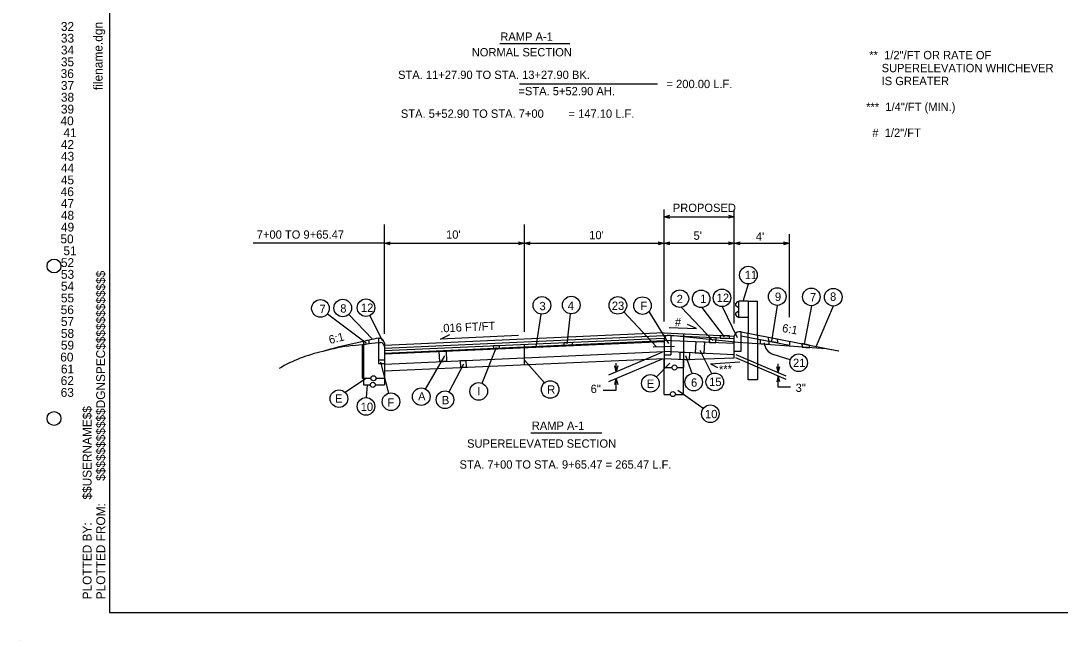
# Model space of a CAD drawing. Extents: x -210 to 558, y -150 to 205.
# Drawn here: x 417 to 491.9, y -150.3 to -105.6 of the extents above; entities that cross this region are included whole.
import ezdxf

# ---------------------------------------------------------------- set-up
doc = ezdxf.new("R2010")
doc.units = 0
for name, color, linetype in [('Level 1', 7, 'Continuous'), ('Level 32', 7, 'Continuous'), ('Level 33', 7, 'Continuous'), ('Level 34', 7, 'Continuous'), ('Level 35', 7, 'Continuous'), ('Level 36', 7, 'Continuous'), ('Level 37', 7, 'Continuous'), ('Level 38', 7, 'Continuous'), ('Level 39', 7, 'Continuous'), ('Level 4', 7, 'Continuous'), ('Level 40', 7, 'Continuous'), ('Level 41', 7, 'Continuous'), ('Level 42', 7, 'Continuous'), ('Level 43', 7, 'Continuous'), ('Level 44', 7, 'Continuous'), ('Level 45', 7, 'Continuous'), ('Level 46', 7, 'Continuous'), ('Level 47', 7, 'Continuous'), ('Level 48', 7, 'Continuous'), ('Level 49', 7, 'Continuous'), ('Level 50', 7, 'Continuous'), ('Level 51', 7, 'Continuous'), ('Level 52', 7, 'Continuous'), ('Level 53', 7, 'Continuous'), ('Level 54', 7, 'Continuous'), ('Level 55', 7, 'Continuous'), ('Level 56', 7, 'Continuous'), ('Level 57', 7, 'Continuous'), ('Level 58', 7, 'Continuous'), ('Level 59', 7, 'Continuous'), ('Level 6', 7, 'Continuous'), ('Level 60', 7, 'Continuous'), ('Level 61', 7, 'Continuous'), ('Level 62', 7, 'Continuous'), ('Level 63', 7, 'Continuous'), ('Level 7', 7, 'Continuous')]:
    doc.layers.add(name, color=color, linetype=linetype)

msp = doc.modelspace()

# ---------------------------------------------------------------- linework, layer by layer
at = {"layer": 'Level 1'}
for p, q in [((423.408, -64.342), (423.408, -148.31)), ((423.408, -148.31), (557.356, -148.31)), ((417.012, -150.31), (417.012, -150.31))]:
    msp.add_line(p, q, dxfattribs=at)
for centre in [(419.41, -123.32), (419.41, -134.316)]:
    msp.add_circle(centre, 0.5, dxfattribs=at)
at = {"layer": 'Level 4'}
for p, q in [((451.546, -107.277), (456.581, -107.277)), ((452.962, -110.192), (462.91, -110.192)), ((463.379, -127.312), (463.379, -119.248)), ((463.379, -119.766), (468.44, -119.766)), ((468.44, -127.46), (468.44, -119.248)), ((443.221, -128.224), (443.221, -120.323)), ((453.3, -120.323), (453.3, -128.073)), ((472.416, -127.011), (472.416, -121.017)), ((443.221, -121.681), (433.765, -121.681)), ((443.221, -121.681), (453.3, -121.681)), ((453.3, -121.681), (472.416, -121.681)), ((469.085, -125.864), (469.461, -124.609)), ((462.294, -126.604), (463.705, -128.917)), ((464.635, -126.302), (466.891, -128.686)), ((466.104, -126.322), (467.709, -128.435)), ((467.558, -126.247), (468.643, -128.468)), ((471.537, -126.158), (471.133, -128.733)), ((473.998, -126.182), (473.483, -128.946)), ((475.576, -126.205), (474.335, -129.112)), ((439.121, -126.759), (441.913, -128.85)), ((440.658, -126.812), (442.358, -128.602)), ((442.175, -126.895), (443.064, -128.693)), ((454.487, -126.787), (454.142, -129.143)), ((456.621, -126.766), (456.375, -128.93)), ((460.477, -126.63), (462.838, -129.148)), ((463.76, -127.746), (465.712, -127.833)), ((465.712, -127.833), (465.08, -127.529)), ((447.268, -128.589), (447.933, -128.269)), ((452.893, -128.336), (447.268, -128.589)), ((450.258, -131.776), (451.299, -129.177)), ((463.221, -129.555), (459.385, -131.187)), ((466.814, -131.089), (465.985, -129.403)), ((443.537, -132.496), (442.959, -130.262)), ((446.195, -132.195), (447.574, -129.805)), ((447.886, -132.405), (448.959, -130.367)), ((454.754, -131.75), (453.31, -130.11)), ((463.253, -130.039), (459.385, -131.685)), ((459.939, -130.951), (459.939, -130.322)), ((462.836, -131.325), (463.792, -130.325)), ((465.414, -131.069), (464.958, -129.808)), ((466.729, -130.375), (468.833, -130.225)), ((468.524, -129.93), (472.169, -131.481)), ((468.554, -129.702), (472.159, -131.236)), ((472.481, -130.097), (471.24, -129.697)), ((466.729, -130.375), (467.243, -130.639)), ((471.604, -131), (471.604, -130.37)), ((441.93, -131.418), (440.392, -132.439)), ((459.939, -132.264), (459.939, -131.449)), ((471.614, -132.06), (471.614, -131.245)), ((441.981, -131.88), (441.898, -132.812)), ((458.98, -132.264), (459.939, -132.264)), ((466.2, -133.609), (464.367, -132.309)), ((472.49, -132.06), (471.614, -132.06)), ((453.788, -135.345), (458.897, -135.345))]:
    msp.add_line(p, q, dxfattribs=at)
for points in [[(463.799, -119.882), (463.379, -119.766), (463.799, -119.654)], [(468.02, -119.65), (468.44, -119.766), (468.02, -119.878)], [(443.641, -121.797), (443.221, -121.681), (443.641, -121.569)], [(452.88, -121.565), (453.3, -121.681), (452.88, -121.793)], [(453.72, -121.797), (453.3, -121.681), (453.72, -121.569)], [(462.959, -121.565), (463.379, -121.681), (462.959, -121.793)], [(463.799, -121.797), (463.379, -121.681), (463.799, -121.569)], [(468.02, -121.565), (468.44, -121.681), (468.02, -121.793)], [(468.86, -121.797), (468.44, -121.681), (468.86, -121.569)], [(471.996, -121.565), (472.416, -121.681), (471.996, -121.793)], [(460.055, -130.531), (459.939, -130.951), (459.827, -130.531)], [(471.488, -130.58), (471.604, -131), (471.716, -130.58)], [(459.823, -131.869), (459.939, -131.449), (460.051, -131.869)], [(471.73, -131.665), (471.614, -131.245), (471.502, -131.665)]]:
    msp.add_lwpolyline(points, dxfattribs=at)
for points in [[(470.336, -128.625), (470.929, -128.742), (470.931, -128.975), (470.342, -128.935)], [(470.914, -128.455), (471.527, -128.576), (471.548, -128.867), (470.935, -128.746)], [(473.307, -128.915), (473.327, -129.18), (473.867, -129.231), (473.853, -129.034)]]:
    msp.add_lwpolyline(points, close=True, dxfattribs=at)
for centre in [(469.462, -123.975), (464.521, -125.678), (466.054, -125.69), (467.559, -125.613), (471.539, -125.524), (473.999, -125.548), (475.577, -125.571), (438.613, -126.378), (440.221, -126.352), (441.895, -126.326), (454.579, -126.16), (456.693, -126.136), (460.052, -126.16), (461.825, -126.177), (473.083, -130.297), (465.517, -131.694), (467.038, -131.682), (450.022, -132.365), (455.173, -132.226), (462.398, -131.783), (439.946, -132.89), (443.695, -133.11), (445.878, -132.744), (447.591, -132.966), (441.898, -133.446), (466.717, -133.975)]:
    msp.add_circle(centre, 0.634, dxfattribs=at)
msp.add_arc((471.57, -128.788), 0.967, 184.63452, 250.04639, dxfattribs=at)
at = {"layer": 'Level 6'}
for p, q in [((442.798, -128.83), (442.798, -130.356)), ((442.798, -128.83), (442.952, -128.83)), ((443.221, -129.418), (463.379, -128.513)), ((443.221, -129.659), (463.379, -128.754)), ((463.379, -128.513), (463.379, -130.639)), ((463.652, -128.302), (463.879, -128.302)), ((463.879, -128.302), (468.713, -128.812)), ((463.879, -128.302), (463.879, -129.718)), ((464.781, -128.213), (464.781, -130.639)), ((468.713, -128.812), (475.073, -129.274)), ((441.626, -128.976), (441.626, -131.418)), ((443.221, -129.122), (443.221, -131.418)), ((443.221, -130.393), (463.379, -129.488)), ((453.3, -128.966), (453.3, -130.438)), ((475.073, -129.274), (475.991, -129.448)), ((442.798, -130.356), (443.221, -130.356)), ((443.221, -130.89), (463.379, -129.985)), ((463.379, -129.718), (463.879, -129.718)), ((463.379, -130.639), (463.952, -130.639)), ((464.31, -130.639), (464.781, -130.639)), ((441.626, -131.418), (442.217, -131.418)), ((442.607, -131.418), (443.221, -131.418))]:
    msp.add_line(p, q, dxfattribs=at)
for centre in [(464.136, -130.639), (442.396, -131.888), (442.427, -131.419)]:
    msp.add_circle(centre, 0.183, dxfattribs=at)
for centre, radius, start, end in [((354.524, 574.72), 709.066, 276.998467, 277.151492), ((442.867, -129.178), 0.359, 8.91155, 76.24656), ((463.74, -128.654), 0.363, 103.89297, 186.01636), ((441.075, -140.015), 10.774, 102.28567, 120.31113), ((442.199, -141.09), 12.095, 96.07186, 106.45302)]:
    msp.add_arc(centre, radius, start, end, dxfattribs=at)
at = {"layer": 'Level 60'}
for points in [[(441.718, -128.964), (442.123, -128.914), (442.115, -128.661), (441.7, -128.754)], [(456.184, -129.077), (456.174, -128.837), (456.754, -128.811), (456.764, -129.051)], [(466.283, -129.619), (466.319, -128.823), (465.665, -128.793), (465.629, -129.589)], [(467.121, -128.854), (467.137, -128.5), (466.657, -128.479), (466.641, -128.833)], [(468.098, -128.545), (468.107, -128.359), (467.434, -128.329), (467.426, -128.515)], [(447.207, -130.214), (447.174, -129.482), (447.671, -129.459), (447.704, -130.192)], [(451.103, -129.305), (451.092, -129.065), (451.494, -129.047), (451.505, -129.287)], [(464.512, -130.049), (464.906, -130.067), (465.217, -130.056), (465.248, -129.578), (464.526, -129.547)], [(448.729, -130.643), (448.707, -130.147), (449.085, -130.13), (449.107, -130.626)]]:
    msp.add_lwpolyline(points, close=True, dxfattribs=at)
at = {"layer": 'Level 7'}
for p, q in [((468.687, -125.874), (468.774, -125.859)), ((469.441, -125.859), (468.774, -125.859)), ((468.774, -127.025), (468.774, -125.859)), ((469.441, -125.859), (469.441, -128.109)), ((469.441, -125.859), (470.107, -125.859)), ((470.107, -128.361), (470.107, -125.859)), ((468.539, -126.078), (468.687, -125.874)), ((468.744, -126.333), (468.554, -126.186)), ((468.554, -126.698), (468.744, -126.551)), ((468.687, -127.01), (468.539, -126.806)), ((468.687, -127.01), (468.774, -127.025)), ((469.441, -127.025), (468.774, -127.025)), ((468.938, -128.061), (468.778, -128.061)), ((468.938, -128.061), (475.955, -129.428)), ((468.938, -129.467), (468.938, -128.061)), ((469.441, -131.525), (469.441, -128.109)), ((442.798, -128.529), (442.798, -130.085)), ((442.798, -128.529), (442.89, -128.529)), ((463.377, -128.15), (443.221, -129.055)), ((443.221, -129.241), (463.356, -128.337)), ((443.221, -129.596), (463.392, -128.69)), ((463.377, -128.15), (468.438, -128.377)), ((468.46, -128.564), (463.377, -128.336)), ((463.377, -128.691), (463.377, -129.995)), ((468.424, -128.917), (463.377, -128.691)), ((468.438, -129.94), (468.438, -128.377)), ((468.938, -128.353), (472.416, -129.03)), ((470.107, -128.361), (470.107, -131.525)), ((472.416, -128.739), (472.416, -129.03)), ((441.718, -128.976), (441.718, -131.88)), ((443.221, -128.892), (443.221, -130.085)), ((462.588, -129.158), (464.13, -129.096)), ((468.438, -129.715), (463.377, -129.488)), ((468.438, -129.467), (468.938, -129.467)), ((442.798, -130.085), (443.221, -130.085)), ((443.221, -130.085), (443.221, -131.88)), ((463.377, -129.995), (464.906, -130.067)), ((463.379, -132.588), (463.379, -129.982)), ((464.786, -132.588), (464.786, -130.025)), ((464.906, -130.067), (468.438, -129.94)), ((470.107, -131.525), (469.441, -131.525)), ((441.718, -131.88), (442.213, -131.88)), ((442.578, -131.88), (443.221, -131.88)), ((463.379, -132.588), (463.841, -132.588)), ((464.2, -132.588), (464.786, -132.588))]:
    msp.add_line(p, q, dxfattribs=at)
msp.add_circle((464.02, -132.561), 0.18, dxfattribs=at)
for centre, radius, start, end in [((468.602, -126.124), 0.0781, 144.08393, 232.1285), ((468.696, -126.489), 0.0781, 307.8715, 360), ((468.602, -126.76), 0.0781, 127.8715, 215.91607), ((468.819, -128.446), 0.387, 96.02749, 169.67861), ((447.357, -157.769), 29.551, 101.48467, 106.57547), ((445.961, -146.756), 18.499, 99.84483, 104.04247), ((442.823, -128.924), 0.4, 4.50116, 80.36352)]:
    msp.add_arc(centre, radius, start, end, dxfattribs=at)

# ---------------------------------------------------------------- texts
at = {"layer": 'Level 1'}
for s, height, p in [('filename.dgn', 0.6414, (422.904, -110.628)), ('$$$$$$$$$$$DGNSPEC$$$$$$$$$$$$', 0.63883, (423.088, -138.812)), ('$$USERNAME$$', 0.63833, (422.11, -140.163)), ('PLOTTED FROM:', 0.63883, (423.095, -147.356)), ('PLOTTED BY:', 0.63883, (422.11, -147.363))]:
    msp.add_text(s, height=height, rotation=90, dxfattribs=at).set_placement(p)
at = {"layer": 'Level 32'}
msp.add_text('32', height=0.6384, dxfattribs=at).set_placement((419.904, -106.36))
at = {"layer": 'Level 33'}
msp.add_text('33', height=0.6384, dxfattribs=at).set_placement((419.904, -107.208))
at = {"layer": 'Level 34'}
msp.add_text('34', height=0.6378, dxfattribs=at).set_placement((419.904, -108.063))
at = {"layer": 'Level 35'}
msp.add_text('35', height=0.6378, dxfattribs=at).set_placement((419.904, -108.918))
at = {"layer": 'Level 36'}
msp.add_text('36', height=0.6384, dxfattribs=at).set_placement((419.888, -109.765))
at = {"layer": 'Level 37'}
msp.add_text('37', height=0.6414, dxfattribs=at).set_placement((419.904, -110.621))
at = {"layer": 'Level 38'}
msp.add_text('38', height=0.6384, dxfattribs=at).set_placement((419.904, -111.468))
at = {"layer": 'Level 39'}
msp.add_text('39', height=0.6384, dxfattribs=at).set_placement((419.904, -112.323))
at = {"layer": 'Level 4'}
for s, p in [('RAMP A-1', (451.578, -107.078)), ('NORMAL SECTION', (449.517, -108.202)), (' **  1/2"/FT OR RATE OF', (477.949, -108.408)), ('STA. 11+27.90 TO STA. 13+27.90 BK. ', (444.207, -109.83)), ('     SUPERELEVATION WHICHEVER', (477.949, -109.342)), ('= 200.00 L.F.', (463.559, -110.491)), ('     IS GREATER', (477.949, -110.275)), ('=STA. 5+52.90 AH. ', (452.883, -111.007)), ('***  1/4"/FT (MIN.)', (477.949, -112.142)), ('STA. 5+52.90 TO STA. 7+00        = 147.10 L.F.', (444.409, -112.632)), ('  #  1/2"/FT', (477.949, -114.008)), ('PROPOSED', (464.013, -119.423)), ('7+00 TO 9+65.47', (434.023, -121.351)), ("10'", (447.666, -121.352)), ("10'", (457.987, -121.39)), ("5'", (465.507, -121.429)), ("4'", (470.001, -121.488)), ('11', (469.197, -124.263)), ('2', (464.292, -125.998)), ('1', (465.979, -125.986)), ('12', (467.175, -125.91)), ('9', (471.372, -125.84)), ('7', (473.896, -125.865)), ('8', (475.346, -125.828)), ('7', (438.54, -126.719)), ('8', (440.044, -126.68)), ('12', (441.534, -126.627)), ('3', (454.403, -126.51)), ('4', (456.437, -126.486)), ('23', (459.618, -126.486)), ('F', (461.671, -126.501)), ('#', (464.165, -127.66)), ('21', (472.678, -130.605)), ('E', (462.141, -132.11)), ('6', (465.324, -132.027)), ('15', (466.63, -131.979)), ('3"', (472.865, -132.402)), ('E', (439.664, -133.177)), ('A', (445.652, -133.02)), ('I', (449.914, -132.654)), ('R', (454.957, -132.526)), ('6"', (458.088, -132.483)), ('10', (441.515, -133.777)), ('F', (443.44, -133.464)), ('B', (447.364, -133.294)), ('10', (466.334, -134.295)), ('RAMP A-1', (453.847, -135.137)), ('SUPERELEVATED SECTION', (449.182, -136.425)), ('STA. 7+00 TO STA. 9+65.47 = 265.47 L.F.', (448.64, -137.935))]:
    msp.add_text(s, height=0.6, dxfattribs=at).set_placement(p)
for s, rotation, p in [('.016 FT/FT', 2.57074, (447.259, -128.112)), ('6:1', 349.97694, (471.858, -128.07)), ('6:1', 13.92183, (439.293, -128.948)), ('***', 4.07739, (467.368, -131.091))]:
    msp.add_text(s, height=0.6, rotation=rotation, dxfattribs=at).set_placement(p)
at = {"layer": 'Level 40'}
msp.add_text('40', height=0.6409, dxfattribs=at).set_placement((419.873, -113.171))
at = {"layer": 'Level 41'}
msp.add_text('41', height=0.6384, dxfattribs=at).set_placement((420.087, -114.026))
at = {"layer": 'Level 42'}
msp.add_text('42', height=0.6384, dxfattribs=at).set_placement((419.904, -114.874))
at = {"layer": 'Level 43'}
msp.add_text('43', height=0.6414, dxfattribs=at).set_placement((419.904, -115.729))
at = {"layer": 'Level 44'}
msp.add_text('44', height=0.6378, dxfattribs=at).set_placement((419.904, -116.576))
at = {"layer": 'Level 45'}
msp.add_text('45', height=0.6384, dxfattribs=at).set_placement((419.904, -117.432))
at = {"layer": 'Level 46'}
msp.add_text('46', height=0.6414, dxfattribs=at).set_placement((419.888, -118.279))
at = {"layer": 'Level 47'}
msp.add_text('47', height=0.6384, dxfattribs=at).set_placement((419.904, -119.134))
at = {"layer": 'Level 48'}
msp.add_text('48', height=0.6384, dxfattribs=at).set_placement((419.904, -119.982))
at = {"layer": 'Level 49'}
msp.add_text('49', height=0.6414, dxfattribs=at).set_placement((419.904, -120.837))
at = {"layer": 'Level 50'}
msp.add_text('50', height=0.6378, dxfattribs=at).set_placement((419.873, -121.685))
at = {"layer": 'Level 51'}
msp.add_text('51', height=0.6384, dxfattribs=at).set_placement((420.087, -122.54))
at = {"layer": 'Level 52'}
msp.add_text('52', height=0.6384, dxfattribs=at).set_placement((419.904, -123.395))
at = {"layer": 'Level 53'}
msp.add_text('53', height=0.6414, dxfattribs=at).set_placement((419.904, -124.243))
at = {"layer": 'Level 54'}
msp.add_text('54', height=0.6378, dxfattribs=at).set_placement((419.904, -125.098))
at = {"layer": 'Level 55'}
msp.add_text('55', height=0.6384, dxfattribs=at).set_placement((419.904, -125.945))
at = {"layer": 'Level 56'}
msp.add_text('56', height=0.6378, dxfattribs=at).set_placement((419.888, -126.793))
at = {"layer": 'Level 57'}
msp.add_text('57', height=0.6384, dxfattribs=at).set_placement((419.904, -127.648))
at = {"layer": 'Level 58'}
msp.add_text('58', height=0.6378, dxfattribs=at).set_placement((419.904, -128.503))
at = {"layer": 'Level 59'}
msp.add_text('59', height=0.6378, dxfattribs=at).set_placement((419.904, -129.351))
at = {"layer": 'Level 60'}
msp.add_text('60', height=0.6378, dxfattribs=at).set_placement((419.858, -130.206))
at = {"layer": 'Level 61'}
msp.add_text('61', height=0.6384, dxfattribs=at).set_placement((419.904, -131.069))
at = {"layer": 'Level 62'}
msp.add_text('62', height=0.6414, dxfattribs=at).set_placement((419.888, -131.909))
at = {"layer": 'Level 63'}
msp.add_text('63', height=0.6384, dxfattribs=at).set_placement((419.888, -132.756))

doc.saveas('drawing.dxf')
